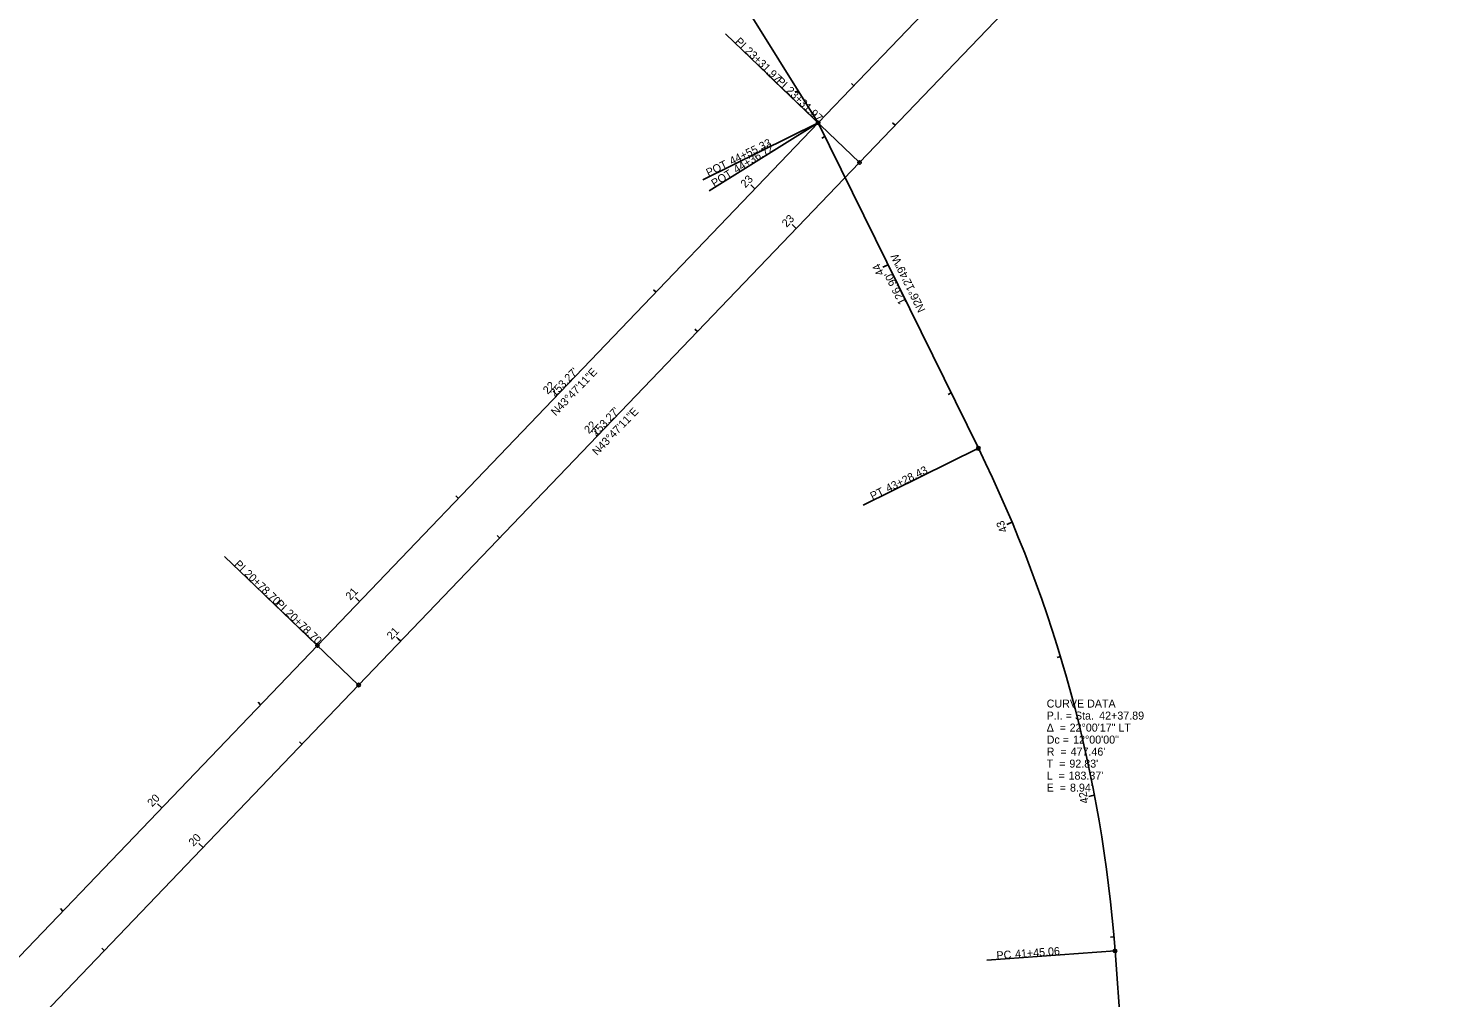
# Model space of a CAD drawing. Extents: x 1363001 to 1363920, y 487582 to 489802.
# Drawn here: x 1363348.2 to 1363838.4, y 488594.8 to 488934.2 of the extents above; entities that cross this region are included whole.
import ezdxf

# ---------------------------------------------------------------- set-up
doc = ezdxf.new("R2010")
doc.units = 0
for name, color, linetype in [('BR_X_SV_Beam_Seat', 7, 'Continuous'), ('BR_X_SV_Bottom_of_Beam_Text', 7, 'Continuous'), ('BR_X_SV_Deck_Top', 7, 'Continuous'), ('BR_X_SV_Deck_Top_Text', 7, 'Continuous'), ('BR_X_SV_Shot_Marker', 7, 'Continuous'), ('DR_X_Cells', 7, 'Continuous'), ('DR_X_Elev_Flow', 7, 'Continuous'), ('PV_X_COP', 7, 'Continuous'), ('PV_X_Curb', 7, 'Continuous'), ('PV_X_EOP', 7, 'Continuous'), ('PV_X_Shoulder_Aggregate', 7, 'Continuous'), ('RD_X_Cells', 7, 'Continuous'), ('RD_X_Concrete_Pad', 7, 'Continuous'), ('RD_X_GR_Lt', 7, 'Continuous'), ('RD_X_GR_Rt', 7, 'Continuous'), ('SG_X_Interconnect_Cable', 7, 'Continuous'), ('SG_X_PullBox', 7, 'Continuous'), ('SN_X_Public', 7, 'Continuous'), ('SV_P_Aerial_Targets', 7, 'Continuous'), ('SV_P_Control_Cells_Set', 7, 'Continuous'), ('SV_P_Mon_Cells_Set', 7, 'Continuous'), ('SV_X_Break_Lines', 7, 'Continuous'), ('SV_X_Mon_Cells_Found', 7, 'Continuous'), ('SV_X_Random_Point', 7, 'Continuous'), ('SV_X_Shot_Marker', 7, 'Continuous'), ('SV_X_Text_Comment', 7, 'Continuous'), ('SV_X_Text_Name', 7, 'Continuous'), ('UT_X_Electric', 7, 'Continuous'), ('UT_X_Electric_Cells', 7, 'Continuous'), ('UT_X_Misc_Cells', 7, 'Continuous'), ('UT_X_Water', 7, 'Continuous')]:
    doc.layers.add(name, color=color, linetype=linetype)

msp = doc.modelspace()

# ---------------------------------------------------------------- linework, layer by layer
at = {"layer": 'BR_X_SV_Bottom_of_Beam_Text'}
for p, q in [((1363624.69, 488900.96), (1363592.2, 488932.1)), ((1363624.69, 488900.96), (1363584.32, 488881.08)), ((1363624.69, 488900.96), (1363586.51, 488877.15)), ((1363680.75, 488787.11), (1363640.37, 488767.23)), ((1363449.43, 488718.12), (1363416.95, 488749.25)), ((1363728.56, 488611.25), (1363683.68, 488607.95))]:
    msp.add_line(p, q, dxfattribs=at)
for centre in [(1363624.69, 488900.96), (1363624.69, 488900.96), (1363624.69, 488900.96), (1363680.75, 488787.11), (1363449.43, 488718.12), (1363728.56, 488611.25)]:
    msp.add_circle(centre, 0.6, dxfattribs=at)
at = {"layer": 'BR_X_SV_Deck_Top'}
for p, q in [((1363651.6, 488900.13), (1363650.74, 488900.96)), ((1363617.01, 488864.04), (1363615.56, 488865.42)), ((1363582.41, 488827.94), (1363581.54, 488828.77)), ((1363547.81, 488791.85), (1363546.37, 488793.23)), ((1363513.21, 488755.75), (1363512.34, 488756.58)), ((1363478.61, 488719.65), (1363477.17, 488721.04)), ((1363444.01, 488683.56), (1363443.15, 488684.39)), ((1363409.41, 488647.46), (1363407.97, 488648.84)), ((1363374.82, 488611.36), (1363373.95, 488612.2))]:
    msp.add_line(p, q, dxfattribs=at)
at = {"layer": 'BR_X_SV_Deck_Top_Text'}
for p, q in [((1363639.13, 488887.12), (1363838.44, 489095.06)), ((1363463.87, 488704.28), (1363639.13, 488887.12)), ((1363094.57, 488318.99), (1363463.87, 488704.28))]:
    msp.add_line(p, q, dxfattribs=at)
at = {"layer": 'BR_X_SV_Shot_Marker'}
for p, q in [((1363637.17, 488913.97), (1363636.3, 488914.8)), ((1363617.66, 488912.23), (1363616.65, 488911.59)), ((1363627.05, 488896.18), (1363625.97, 488895.65)), ((1363602.57, 488877.88), (1363601.12, 488879.26)), ((1363649.13, 488851.32), (1363647.34, 488850.44)), ((1363567.97, 488841.78), (1363567.1, 488842.61)), ((1363533.37, 488805.69), (1363531.93, 488807.07)), ((1363671.22, 488806.46), (1363670.14, 488805.93)), ((1363498.77, 488769.59), (1363497.91, 488770.42)), ((1363692.54, 488761.25), (1363690.69, 488760.47)), ((1363464.17, 488733.49), (1363462.73, 488734.88)), ((1363709.47, 488714.22), (1363708.32, 488713.88)), ((1363429.57, 488697.4), (1363428.71, 488698.23)), ((1363721.39, 488665.69), (1363719.43, 488665.31)), ((1363394.98, 488661.3), (1363393.53, 488662.68)), ((1363360.38, 488625.2), (1363359.51, 488626.03)), ((1363728.17, 488616.17), (1363726.98, 488616.07))]:
    msp.add_line(p, q, dxfattribs=at)
at = {"layer": 'PV_X_COP'}
for p, q in [((1363617.01, 488864.04), (1363616.14, 488864.87)), ((1363547.81, 488791.85), (1363546.94, 488792.68)), ((1363478.61, 488719.65), (1363477.75, 488720.48)), ((1363409.41, 488647.46), (1363407.97, 488648.84))]:
    msp.add_line(p, q, dxfattribs=at)
at = {"layer": 'PV_X_Curb'}
for p, q in [((1363624.69, 488900.96), (1363592.2, 488932.1)), ((1363624.69, 488900.96), (1363584.32, 488881.08)), ((1363624.69, 488900.96), (1363586.51, 488877.15)), ((1363680.75, 488787.11), (1363640.37, 488767.23)), ((1363449.43, 488718.12), (1363416.95, 488749.25)), ((1363728.56, 488611.25), (1363683.68, 488607.95))]:
    msp.add_line(p, q, dxfattribs=at)
for centre in [(1363624.69, 488900.96), (1363624.69, 488900.96), (1363624.69, 488900.96), (1363680.75, 488787.11), (1363449.43, 488718.12), (1363728.56, 488611.25)]:
    msp.add_circle(centre, 0.6, dxfattribs=at)
at = {"layer": 'PV_X_Shoulder_Aggregate'}
for p, q in [((1363639.13, 488887.12), (1363606.64, 488918.26)), ((1363463.87, 488704.28), (1363431.39, 488735.42))]:
    msp.add_line(p, q, dxfattribs=at)
for centre in [(1363639.13, 488887.12), (1363463.87, 488704.28)]:
    msp.add_circle(centre, 0.6, dxfattribs=at)
at = {"layer": 'RD_X_Concrete_Pad'}
for p, q in [((1363639.13, 488887.12), (1363606.64, 488918.26)), ((1363463.87, 488704.28), (1363431.39, 488735.42))]:
    msp.add_line(p, q, dxfattribs=at)
for centre in [(1363639.13, 488887.12), (1363463.87, 488704.28)]:
    msp.add_circle(centre, 0.6, dxfattribs=at)
at = {"layer": 'RD_X_GR_Rt'}
msp.add_line((1363394.98, 488661.3), (1363393.53, 488662.68), dxfattribs=at)
at = {"layer": 'SG_X_PullBox'}
for p, q in [((1363602.57, 488877.88), (1363601.7, 488878.71)), ((1363649.13, 488851.32), (1363648.05, 488850.79)), ((1363533.37, 488805.69), (1363532.5, 488806.52)), ((1363692.54, 488761.25), (1363691.43, 488760.78)), ((1363464.17, 488733.49), (1363463.31, 488734.32)), ((1363721.39, 488665.69), (1363720.21, 488665.46)), ((1363394.98, 488661.3), (1363393.53, 488662.68))]:
    msp.add_line(p, q, dxfattribs=at)
at = {"layer": 'SN_X_Public'}
for p, q in [((1363639.13, 488887.12), (1363606.64, 488918.26)), ((1363463.87, 488704.28), (1363431.39, 488735.42))]:
    msp.add_line(p, q, dxfattribs=at)
for centre in [(1363639.13, 488887.12), (1363463.87, 488704.28)]:
    msp.add_circle(centre, 0.6, dxfattribs=at)
at = {"layer": 'SV_X_Shot_Marker'}
for p, q in [((1363680.75, 488787.11), (1363624.69, 488900.96)), ((1363625.29, 488900.96), (1363625.29, 488900.96)), ((1363728.56, 488611.25), (1363748.75, 488336.93))]:
    msp.add_line(p, q, dxfattribs=at)
msp.add_arc((1363252.39, 488576.21), 477.46, 4.209, 26.2136, dxfattribs=at)
at = {"layer": 'SV_X_Text_Comment'}
for p, q in [((1363624.69, 488900.96), (1363355.75, 489332.29)), ((1363624.69, 488900.96), (1363824, 489108.89)), ((1363449.43, 488718.12), (1363624.69, 488900.96)), ((1363680.75, 488787.11), (1363624.69, 488900.96)), ((1363080.13, 488332.82), (1363449.43, 488718.12)), ((1363748.75, 488336.93), (1363728.56, 488611.25))]:
    msp.add_line(p, q, dxfattribs=at)
msp.add_arc((1363252.39, 488576.21), 477.46, 4.209, 26.2136, dxfattribs=at)
at = {"layer": 'SV_X_Text_Name'}
for p, q in [((1363680.08, 488786.44), (1363681.41, 488787.78)), ((1363680.08, 488787.78), (1363681.41, 488786.44))]:
    msp.add_line(p, q, dxfattribs=at)
at = {"layer": 'UT_X_Misc_Cells'}
msp.add_line((1363409.41, 488647.46), (1363407.97, 488648.84), dxfattribs=at)
at = {"layer": 'UT_X_Water'}
for p, q in [((1363624.69, 488900.96), (1363592.2, 488932.1)), ((1363624.69, 488900.96), (1363584.32, 488881.08)), ((1363624.69, 488900.96), (1363586.51, 488877.15)), ((1363680.75, 488787.11), (1363640.37, 488767.23)), ((1363449.43, 488718.12), (1363416.95, 488749.25)), ((1363728.56, 488611.25), (1363683.68, 488607.95))]:
    msp.add_line(p, q, dxfattribs=at)
for centre in [(1363624.69, 488900.96), (1363624.69, 488900.96), (1363624.69, 488900.96), (1363680.75, 488787.11), (1363449.43, 488718.12), (1363728.56, 488611.25)]:
    msp.add_circle(centre, 0.6, dxfattribs=at)

# ---------------------------------------------------------------- texts
at = {"layer": 'BR_X_SV_Beam_Seat'}
for s, rotation, p in [('N26°12\'49"W', 116.2136, (1363662.27, 488835.51)), ('N43°47\'11"E', 46.2136, (1363532.89, 488798.25))]:
    msp.add_text(s, height=2.8, rotation=rotation, dxfattribs=at).set_placement(p)
at = {"layer": 'BR_X_SV_Bottom_of_Beam_Text'}
for s, rotation, p in [('PI', 316.2136, (1363595.36, 488929.14)), ('23+31.97', 316.2136, (1363598.81, 488925.83)), ('44+55.33', 26.2136, (1363594.48, 488886.14)), ('44+36.72', 31.9439, (1363596.11, 488883.19)), ('POT', 26.2136, (1363586.29, 488882.11)), ('POT', 31.9439, (1363588.36, 488878.36)), ('43+28.43', 26.2136, (1363649.17, 488771.62)), ('PT', 26.2136, (1363643.71, 488768.93)), ('PI', 316.2136, (1363420.14, 488746.26)), ('20+78.70', 316.2136, (1363423.6, 488742.95)), ('PC', 4.209, (1363687.18, 488608.25)), ('41+45.06', 4.209, (1363693.68, 488608.73))]:
    msp.add_text(s, height=2.8, rotation=rotation, dxfattribs=at).set_placement(p)
at = {"layer": 'BR_X_SV_Deck_Top'}
for s, p in [('23', (1363613.66, 488864.23)), ('22', (1363544.49, 488792)), ('21', (1363475.41, 488719.92)), ('20', (1363406.06, 488647.64))]:
    msp.add_text(s, height=2.8, rotation=46.2136, dxfattribs=at).set_placement(p)
at = {"layer": 'BR_X_SV_Shot_Marker'}
for s, rotation, p in [('23', 46.2136, (1363599.22, 488878.07)), ('44', 116.2136, (1363647.84, 488848.28)), ('22', 46.2136, (1363530.05, 488805.84)), ('43', 112.802, (1363691.03, 488758.25)), ('21', 46.2136, (1363460.97, 488733.76)), ('20', 46.2136, (1363391.62, 488661.48)), ('42', 100.8018, (1363719.34, 488663.07))]:
    msp.add_text(s, height=2.8, rotation=rotation, dxfattribs=at).set_placement(p)
at = {"layer": 'DR_X_Cells'}
for s, rotation, p in [("126.90'", 116.2136, (1363655.54, 488838.19)), ("253.27'", 46.2136, (1363532.54, 488804.89))]:
    msp.add_text(s, height=2.8, rotation=rotation, dxfattribs=at).set_placement(p)
at = {"layer": 'DR_X_Elev_Flow'}
for s, p in [('CURVE DATA', (1363704.65, 488696.38)), ('P.I. = Sta. ', (1363704.65, 488692.18)), ('42+37.89', (1363723.02, 488692.18)), ('Δ  = ', (1363704.65, 488687.98)), ('22°00\'17" LT', (1363712.68, 488687.98)), ('Dc = ', (1363704.65, 488683.78)), ('12°00\'00"', (1363713.89, 488683.78)), ('R  = ', (1363704.65, 488679.58)), ("477.46'", (1363713.02, 488679.58)), ('T  = ', (1363704.65, 488675.38)), ('L  = ', (1363704.65, 488671.18)), ("183.37'", (1363712.3, 488671.18)), ("92.83'", (1363712.59, 488675.38)), ('E  = ', (1363704.65, 488666.98)), ("8.94'", (1363712.81, 488666.98))]:
    msp.add_text(s, height=2.8, dxfattribs=at).set_placement(p)
at = {"layer": 'PV_X_COP'}
msp.add_text('20', height=2.8, rotation=46.2136, dxfattribs=at).set_placement((1363406.06, 488647.64))
at = {"layer": 'PV_X_Curb'}
for s, rotation, p in [('PI', 316.2136, (1363595.36, 488929.14)), ('23+31.97', 316.2136, (1363598.81, 488925.83)), ('44+55.33', 26.2136, (1363594.48, 488886.14)), ('44+36.72', 31.9439, (1363596.11, 488883.19)), ('POT', 26.2136, (1363586.29, 488882.11)), ('POT', 31.9439, (1363588.36, 488878.36)), ('43+28.43', 26.2136, (1363649.17, 488771.62)), ('PT', 26.2136, (1363643.71, 488768.93)), ('PI', 316.2136, (1363420.14, 488746.26)), ('20+78.70', 316.2136, (1363423.6, 488742.95)), ('PC', 4.209, (1363687.18, 488608.25)), ('41+45.06', 4.209, (1363693.68, 488608.73))]:
    msp.add_text(s, height=2.8, rotation=rotation, dxfattribs=at).set_placement(p)
at = {"layer": 'PV_X_EOP'}
msp.add_text('N43°47\'11"E', height=2.8, rotation=46.2136, dxfattribs=at).set_placement((1363547.33, 488784.41))
at = {"layer": 'PV_X_Shoulder_Aggregate'}
for s, p in [('PI', (1363609.8, 488915.3)), ('23+31.97', (1363613.25, 488911.99)), ('PI', (1363434.58, 488732.42)), ('20+78.70', (1363438.03, 488729.11))]:
    msp.add_text(s, height=2.8, rotation=316.2136, dxfattribs=at).set_placement(p)
at = {"layer": 'RD_X_Cells'}
msp.add_text('N43°47\'11"E', height=2.8, rotation=46.2136, dxfattribs=at).set_placement((1363547.33, 488784.41))
at = {"layer": 'RD_X_Concrete_Pad'}
for s, p in [('PI', (1363609.8, 488915.3)), ('23+31.97', (1363613.25, 488911.99)), ('PI', (1363434.58, 488732.42)), ('20+78.70', (1363438.03, 488729.11))]:
    msp.add_text(s, height=2.8, rotation=316.2136, dxfattribs=at).set_placement(p)
at = {"layer": 'RD_X_GR_Lt'}
for s, rotation, p in [("126.90'", 116.2136, (1363655.54, 488838.19)), ("253.27'", 46.2136, (1363532.54, 488804.89))]:
    msp.add_text(s, height=2.8, rotation=rotation, dxfattribs=at).set_placement(p)
at = {"layer": 'RD_X_GR_Rt'}
msp.add_text('20', height=2.8, rotation=46.2136, dxfattribs=at).set_placement((1363391.62, 488661.48))
at = {"layer": 'SG_X_Interconnect_Cable'}
for s, rotation, p in [('N26°12\'49"W', 116.2136, (1363662.27, 488835.51)), ('N43°47\'11"E', 46.2136, (1363532.89, 488798.25))]:
    msp.add_text(s, height=2.8, rotation=rotation, dxfattribs=at).set_placement(p)
at = {"layer": 'SG_X_PullBox'}
msp.add_text('20', height=2.8, rotation=46.2136, dxfattribs=at).set_placement((1363391.62, 488661.48))
at = {"layer": 'SN_X_Public'}
for s, p in [('PI', (1363609.8, 488915.3)), ('23+31.97', (1363613.25, 488911.99)), ('PI', (1363434.58, 488732.42)), ('20+78.70', (1363438.03, 488729.11))]:
    msp.add_text(s, height=2.8, rotation=316.2136, dxfattribs=at).set_placement(p)
at = {"layer": 'SV_P_Aerial_Targets'}
msp.add_text("253.27'", height=2.8, rotation=46.2136, dxfattribs=at).set_placement((1363546.98, 488791.05))
at = {"layer": 'SV_P_Control_Cells_Set'}
for s, p in [('CURVE DATA', (1363704.65, 488696.38)), ('P.I. = Sta. ', (1363704.65, 488692.18)), ('42+37.89', (1363723.02, 488692.18)), ('Δ  = ', (1363704.65, 488687.98)), ('22°00\'17" LT', (1363712.68, 488687.98)), ('Dc = ', (1363704.65, 488683.78)), ('12°00\'00"', (1363713.89, 488683.78)), ('R  = ', (1363704.65, 488679.58)), ("477.46'", (1363713.02, 488679.58)), ('T  = ', (1363704.65, 488675.38)), ('L  = ', (1363704.65, 488671.18)), ("183.37'", (1363712.3, 488671.18)), ("92.83'", (1363712.59, 488675.38)), ('E  = ', (1363704.65, 488666.98)), ("8.94'", (1363712.81, 488666.98))]:
    msp.add_text(s, height=2.8, dxfattribs=at).set_placement(p)
at = {"layer": 'SV_P_Mon_Cells_Set'}
msp.add_text('N43°47\'11"E', height=2.8, rotation=46.2136, dxfattribs=at).set_placement((1363547.33, 488784.41))
at = {"layer": 'SV_X_Break_Lines'}
for s, rotation, p in [("126.90'", 116.2136, (1363655.54, 488838.19)), ("253.27'", 46.2136, (1363532.54, 488804.89))]:
    msp.add_text(s, height=2.8, rotation=rotation, dxfattribs=at).set_placement(p)
at = {"layer": 'SV_X_Mon_Cells_Found'}
msp.add_text("253.27'", height=2.8, rotation=46.2136, dxfattribs=at).set_placement((1363546.98, 488791.05))
at = {"layer": 'SV_X_Random_Point'}
msp.add_text("253.27'", height=2.8, rotation=46.2136, dxfattribs=at).set_placement((1363546.98, 488791.05))
at = {"layer": 'UT_X_Electric'}
for s, p in [('CURVE DATA', (1363704.65, 488696.38)), ('P.I. = Sta. ', (1363704.65, 488692.18)), ('42+37.89', (1363723.02, 488692.18)), ('Δ  = ', (1363704.65, 488687.98)), ('22°00\'17" LT', (1363712.68, 488687.98)), ('Dc = ', (1363704.65, 488683.78)), ('12°00\'00"', (1363713.89, 488683.78)), ('R  = ', (1363704.65, 488679.58)), ("477.46'", (1363713.02, 488679.58)), ('T  = ', (1363704.65, 488675.38)), ('L  = ', (1363704.65, 488671.18)), ("183.37'", (1363712.3, 488671.18)), ("92.83'", (1363712.59, 488675.38)), ('E  = ', (1363704.65, 488666.98)), ("8.94'", (1363712.81, 488666.98))]:
    msp.add_text(s, height=2.8, dxfattribs=at).set_placement(p)
at = {"layer": 'UT_X_Electric_Cells'}
for s, rotation, p in [('N26°12\'49"W', 116.2136, (1363662.27, 488835.51)), ('N43°47\'11"E', 46.2136, (1363532.89, 488798.25))]:
    msp.add_text(s, height=2.8, rotation=rotation, dxfattribs=at).set_placement(p)
at = {"layer": 'UT_X_Misc_Cells'}
msp.add_text('20', height=2.8, rotation=46.2136, dxfattribs=at).set_placement((1363406.06, 488647.64))
at = {"layer": 'UT_X_Water'}
for s, rotation, p in [('PI', 316.2136, (1363595.36, 488929.14)), ('23+31.97', 316.2136, (1363598.81, 488925.83)), ('44+55.33', 26.2136, (1363594.48, 488886.14)), ('44+36.72', 31.9439, (1363596.11, 488883.19)), ('POT', 26.2136, (1363586.29, 488882.11)), ('POT', 31.9439, (1363588.36, 488878.36)), ('43+28.43', 26.2136, (1363649.17, 488771.62)), ('PT', 26.2136, (1363643.71, 488768.93)), ('PI', 316.2136, (1363420.14, 488746.26)), ('20+78.70', 316.2136, (1363423.6, 488742.95)), ('PC', 4.209, (1363687.18, 488608.25)), ('41+45.06', 4.209, (1363693.68, 488608.73))]:
    msp.add_text(s, height=2.8, rotation=rotation, dxfattribs=at).set_placement(p)

doc.saveas('drawing.dxf')
